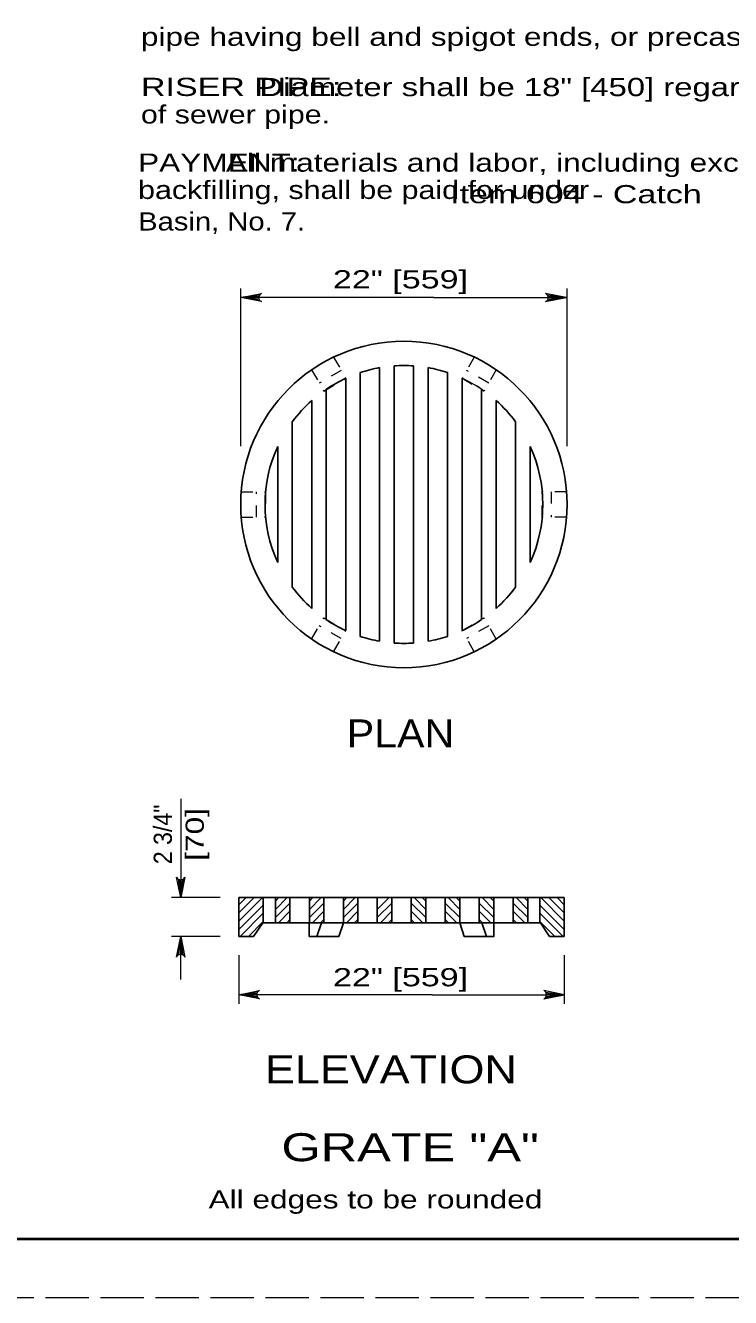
# Model space of a CAD drawing. Extents: x 1302.9 to 1336.9, y 688.5 to 710.5.
# Drawn here: x 1324.42 to 1330.47, y 688.5 to 699.41 of the extents above; entities that cross this region are included whole.
import ezdxf
from ezdxf.enums import TextEntityAlignment as Align

# ---------------------------------------------------------------- set-up
doc = ezdxf.new("R2010")
doc.units = 0
doc.header["$LTSCALE"] = 0.062
doc.linetypes.add('LONG_DASHED', pattern=[7.5, 6, -1.5])
doc.linetypes.add('SHORT_DASHED', pattern=[2.7, 1.5, -1.2])
doc.layers.add('1', color=7, linetype='Continuous', lineweight=13)

msp = doc.modelspace()

# ---------------------------------------------------------------- linework, layer by layer
at = {"layer": '1'}
for p, q in [((1326.26492, 695.80467), (1326.26492, 697.15808)), ((1326.42517, 697.10233), (1326.26492, 697.07992)), ((1326.41975, 697.09125), (1326.26492, 697.07992)), ((1328.89708, 697.10233), (1329.05733, 697.07992)), ((1328.9025, 697.09125), (1329.05733, 697.07992)), ((1329.06583, 695.80467), (1329.06583, 697.15808)), ((1327.922, 697.07992), (1326.26492, 697.07992)), ((1326.41808, 697.07992), (1326.26492, 697.07992)), ((1326.42092, 697.0655), (1326.26492, 697.07992)), ((1326.42708, 697.05517), (1326.26492, 697.07992)), ((1327.922, 697.07992), (1329.05733, 697.07992)), ((1328.89517, 697.05517), (1329.05733, 697.07992)), ((1328.90133, 697.0655), (1329.05733, 697.07992)), ((1328.90417, 697.07992), (1329.05733, 697.07992)), ((1325.74942, 692.78075), (1325.74942, 691.93217)), ((1325.727, 692.09242), (1325.74942, 691.93217)), ((1325.73808, 692.087), (1325.74942, 691.93217)), ((1325.77417, 692.09425), (1325.74942, 691.93217)), ((1325.76383, 692.08817), (1325.74942, 691.93217)), ((1325.74942, 692.08533), (1325.74942, 691.93217)), ((1326.08775, 691.93217), (1325.67125, 691.93217)), ((1326.24917, 691.87108), (1326.31025, 691.93217)), ((1326.24917, 691.8005), (1326.38083, 691.93217)), ((1326.24917, 691.72967), (1326.45167, 691.93217)), ((1326.24917, 691.65908), (1326.45833, 691.86817)), ((1326.5625, 691.90175), (1326.59292, 691.93217)), ((1326.5625, 691.83108), (1326.66358, 691.93217)), ((1326.5625, 691.7605), (1326.68742, 691.88542)), ((1326.85408, 691.90175), (1326.88442, 691.93217)), ((1326.85408, 691.83108), (1326.95508, 691.93217)), ((1326.85408, 691.7605), (1326.979, 691.88542)), ((1327.14558, 691.90175), (1327.176, 691.93217)), ((1327.14558, 691.83108), (1327.24658, 691.93217)), ((1327.14558, 691.7605), (1327.2705, 691.88542)), ((1327.43708, 691.83108), (1327.53817, 691.93217)), ((1327.43708, 691.7605), (1327.56208, 691.88542)), ((1327.85358, 691.7605), (1327.72867, 691.88542)), ((1327.85358, 691.83108), (1327.7525, 691.93217)), ((1327.85358, 691.90175), (1327.82317, 691.93217)), ((1328.14508, 691.7605), (1328.02017, 691.88542)), ((1328.14508, 691.83108), (1328.04408, 691.93217)), ((1328.14508, 691.90175), (1328.11467, 691.93217)), ((1328.43667, 691.7605), (1328.31167, 691.88542)), ((1328.43667, 691.83108), (1328.33558, 691.93217)), ((1328.43667, 691.90175), (1328.40625, 691.93217)), ((1328.72817, 691.7605), (1328.60325, 691.88542)), ((1328.72817, 691.83108), (1328.62717, 691.93217)), ((1328.72817, 691.90175), (1328.69775, 691.93217)), ((1329.0415, 691.65908), (1328.83233, 691.86817)), ((1329.0415, 691.72967), (1328.839, 691.93217)), ((1329.0415, 691.8005), (1328.90983, 691.93217)), ((1329.0415, 691.87108), (1328.9805, 691.93217)), ((1326.25975, 691.599), (1326.45833, 691.79758)), ((1326.58842, 691.71575), (1326.68742, 691.81483)), ((1326.65908, 691.71575), (1326.68742, 691.74417)), ((1326.87992, 691.71575), (1326.979, 691.81483)), ((1326.95058, 691.71575), (1326.979, 691.74417)), ((1327.1715, 691.71575), (1327.2705, 691.81483)), ((1327.24208, 691.71575), (1327.2705, 691.74417)), ((1327.463, 691.71575), (1327.56208, 691.81483)), ((1327.53367, 691.71575), (1327.56208, 691.74417)), ((1327.82767, 691.71575), (1327.72867, 691.81483)), ((1327.757, 691.71575), (1327.72867, 691.74417)), ((1328.11917, 691.71575), (1328.02017, 691.81483)), ((1328.04858, 691.71575), (1328.02017, 691.74417)), ((1328.41075, 691.71575), (1328.31167, 691.81483)), ((1328.34008, 691.71575), (1328.31167, 691.74417)), ((1328.70225, 691.71575), (1328.60325, 691.81483)), ((1328.63158, 691.71575), (1328.60325, 691.74417)), ((1329.03092, 691.599), (1328.83233, 691.79758)), ((1326.3305, 691.599), (1326.45833, 691.72675)), ((1328.96017, 691.599), (1328.83233, 691.72675)), ((1326.08775, 691.599), (1325.67125, 691.599)), ((1325.72458, 691.43692), (1325.74942, 691.599)), ((1325.735, 691.443), (1325.74942, 691.599)), ((1325.74942, 691.479), (1325.74942, 691.599)), ((1325.74942, 691.23042), (1325.74942, 691.599)), ((1325.74942, 691.44583), (1325.74942, 691.599)), ((1325.76075, 691.44417), (1325.74942, 691.599)), ((1325.77183, 691.43875), (1325.74942, 691.599)), ((1326.24917, 691.43758), (1326.24917, 691.02117)), ((1329.0415, 691.43758), (1329.0415, 691.02117)), ((1326.40942, 691.12175), (1326.24917, 691.09933)), ((1326.404, 691.11058), (1326.24917, 691.09933)), ((1327.90625, 691.09933), (1326.24917, 691.09933)), ((1326.40233, 691.09933), (1326.24917, 691.09933)), ((1326.40517, 691.08492), (1326.24917, 691.09933)), ((1326.41133, 691.0745), (1326.24917, 691.09933)), ((1327.90625, 691.09933), (1329.0415, 691.09933)), ((1328.87942, 691.0745), (1329.0415, 691.09933)), ((1328.88125, 691.12175), (1329.0415, 691.09933)), ((1328.8855, 691.08492), (1329.0415, 691.09933)), ((1328.88667, 691.11058), (1329.0415, 691.09933)), ((1328.88833, 691.09933), (1329.0415, 691.09933))]:
    msp.add_line(p, q, dxfattribs=at)
at = {"layer": '1', "linetype": 'SHORT_DASHED'}
for p, q in [((1327.062, 696.56858), (1327.1665, 696.38742)), ((1328.26858, 696.56858), (1328.16408, 696.38742)), ((1326.8725, 696.45917), (1326.97708, 696.27808)), ((1327.12758, 696.45508), (1326.93808, 696.34567)), ((1328.3925, 696.34567), (1328.203, 696.45508)), ((1328.45808, 696.45917), (1328.3535, 696.27808)), ((1326.97708, 696.27808), (1327.1665, 696.38742)), ((1326.26917, 695.41433), (1326.47833, 695.41433)), ((1326.40033, 695.19558), (1326.40033, 695.41433)), ((1326.47833, 695.41433), (1326.47833, 695.19558)), ((1328.85225, 695.19558), (1328.85225, 695.41433)), ((1329.06142, 695.41433), (1328.85225, 695.41433)), ((1328.93025, 695.41433), (1328.93025, 695.19558)), ((1326.26917, 695.19558), (1326.47833, 695.19558)), ((1329.06142, 695.19558), (1328.85225, 695.19558)), ((1326.8725, 694.15067), (1326.97708, 694.33183)), ((1327.12758, 694.15483), (1326.93808, 694.26425)), ((1326.97708, 694.33183), (1327.1665, 694.2225)), ((1328.16408, 694.2225), (1328.3535, 694.33183)), ((1328.3925, 694.26425), (1328.203, 694.15483)), ((1328.45808, 694.15067), (1328.3535, 694.33183)), ((1327.062, 694.04133), (1327.1665, 694.2225)), ((1328.26858, 694.04133), (1328.16408, 694.2225))]:
    msp.add_line(p, q, dxfattribs=at)
at = {"layer": '1', "lineweight": 25}
for p, q in [((1327.2905, 696.43633), (1327.2905, 694.17358)), ((1327.45708, 696.47842), (1327.45708, 694.1315)), ((1327.582, 696.49383), (1327.582, 694.11608)), ((1327.74858, 696.49383), (1327.74858, 694.11608)), ((1327.8735, 696.47842), (1327.8735, 694.1315)), ((1328.04008, 696.43633), (1328.04008, 694.17358)), ((1327.1655, 696.38692), (1327.1655, 694.223)), ((1328.16508, 696.38692), (1328.16508, 694.223)), ((1326.99892, 696.29317), (1326.99892, 694.31675)), ((1328.33167, 696.29317), (1328.33167, 694.31675)), ((1326.874, 696.19625), (1326.874, 694.41367)), ((1328.45658, 696.19625), (1328.45658, 694.41367)), ((1326.70742, 696.01425), (1326.70742, 694.59567)), ((1328.62317, 696.01425), (1328.62317, 694.59567)), ((1326.5825, 695.80308), (1326.5825, 694.80683)), ((1328.74808, 695.80308), (1328.74808, 694.80683)), ((1326.24917, 691.599), (1326.24917, 691.93217)), ((1326.24917, 691.93217), (1329.0415, 691.93217)), ((1326.45833, 691.93217), (1326.45833, 691.71575)), ((1326.5625, 691.93217), (1326.5625, 691.71575)), ((1326.68742, 691.93217), (1326.68742, 691.71575)), ((1326.85408, 691.93217), (1326.85408, 691.71575)), ((1326.979, 691.93217), (1326.979, 691.71575)), ((1327.14558, 691.93217), (1327.14558, 691.71575)), ((1327.2705, 691.93217), (1327.2705, 691.71575)), ((1327.43708, 691.93217), (1327.43708, 691.71575)), ((1327.56208, 691.93217), (1327.56208, 691.71575)), ((1327.72867, 691.93217), (1327.72867, 691.71575)), ((1327.85358, 691.93217), (1327.85358, 691.71575)), ((1328.02017, 691.93217), (1328.02017, 691.71575)), ((1328.14508, 691.93217), (1328.14508, 691.71575)), ((1328.31167, 691.93217), (1328.31167, 691.71575)), ((1328.43667, 691.93217), (1328.43667, 691.71575)), ((1328.60325, 691.93217), (1328.60325, 691.71575)), ((1328.72817, 691.93217), (1328.72817, 691.71575)), ((1328.83233, 691.93217), (1328.83233, 691.71575)), ((1329.0415, 691.599), (1329.0415, 691.93217)), ((1326.45342, 691.71575), (1326.37567, 691.599)), ((1326.45342, 691.71575), (1328.83725, 691.71575)), ((1326.91808, 691.599), (1326.95717, 691.71575)), ((1327.10758, 691.599), (1327.14658, 691.71575)), ((1328.18308, 691.599), (1328.14408, 691.71575)), ((1328.37258, 691.599), (1328.3335, 691.71575)), ((1328.83725, 691.71575), (1328.915, 691.599)), ((1326.24917, 691.599), (1326.37567, 691.599)), ((1329.0415, 691.599), (1328.915, 691.599))]:
    msp.add_line(p, q, dxfattribs=at)
at = {"layer": '1', "linetype": 'SHORT_DASHED', "lineweight": 25}
msp.add_line((1328.16408, 696.38742), (1328.3535, 696.27808), dxfattribs=at)
at = {"layer": '1', "linetype": 'LONG_DASHED'}
msp.add_lwpolyline([(1302.8765, 688.50158), (1336.8765, 688.50158), (1336.8765, 710.50158), (1302.8765, 710.50158)], close=True, dxfattribs=at)
at = {"layer": '1', "lineweight": 25}
for points in [[(1336.3765, 689.00158), (1304.8765, 689.00158), (1304.8765, 710.00158)], [(1326.85258, 691.71575), (1326.85258, 691.599), (1327.10758, 691.599)], [(1328.43817, 691.71575), (1328.43817, 691.599), (1328.18308, 691.599)]]:
    msp.add_lwpolyline(points, dxfattribs=at)
at = {"layer": '1', "lineweight": 40}
msp.add_lwpolyline([(1304.8765, 710.00158), (1336.3765, 710.00158), (1336.3765, 689.00158), (1304.8765, 689.00158)], close=True, dxfattribs=at)
msp.add_lwpolyline([(1304.8765, 710.00158), (1336.3765, 710.00158), (1336.3765, 689.00158), (1304.8765, 689.00158)], close=True, dxfattribs=at)
at = {"layer": '1'}
for points in [[(1326.44192, 697.0445), (1326.26492, 697.07992), (1326.44192, 697.11533)], [(1328.88033, 697.0445), (1329.05733, 697.07992), (1328.88033, 697.11533)], [(1325.78483, 692.10917), (1325.74942, 691.93217), (1325.714, 692.10917)], [(1325.714, 691.422), (1325.74942, 691.599), (1325.78483, 691.422)], [(1326.42617, 691.06392), (1326.24917, 691.09933), (1326.42617, 691.13467)], [(1328.8645, 691.06392), (1329.0415, 691.09933), (1328.8645, 691.13467)]]:
    msp.add_lwpolyline(points, dxfattribs=at)
for centre, start, end in [((1326.45625, 697.08001), 112.08782, 247.91395), ((1328.86601, 697.08001), 292.08605, 67.91218), ((1325.74936, 692.12348), 202.08782, 337.91395), ((1325.74944, 691.40775), 22.08782, 157.91395), ((1326.44046, 691.09937), 112.08782, 247.91395), ((1328.85022, 691.09937), 292.08605, 67.91218)]:
    msp.add_arc(centre, 0.0382, start, end, dxfattribs=at)
at = {"layer": '1', "lineweight": 25}
msp.add_ellipse((1327.66533, 695.30499), major_axis=(1.40038, 0), ratio=0.999895, dxfattribs=at)
for major_axis, start_param, end_param in [((1.19194, 0), 1.74640045, 1.89068977), ((1.19194, 0), 1.50085812, 1.64073453), ((1.19194, 0), 1.25090288, 1.39519221), ((1.19194, 0), 2.00346767, 2.16403195), ((1.19194, 0), 2.2967655, 2.50418527), ((1.19194, 0), 0.63742003, 0.84481261), ((1.19194, 0), 2.71037057, 3.57281474), ((-1.19194, 0), 2.71037057, 3.57281474), ((1.19194, 0), 3.77901269, 3.98640527), ((1.19194, 0), 5.43837269, 5.64576527), ((1.19194, 0), 4.11914987, 4.27972894), ((1.19194, 0), 5.14504902, 5.30562809), ((1.19194, 0), 4.39249553, 4.53678486), ((1.19194, 0), 4.8879931, 5.03228243), ((1.19194, 0), 4.64245078, 4.78232718)]:
    msp.add_ellipse((1327.66529, 695.30499), major_axis=major_axis, ratio=0.999895, start_param=start_param, end_param=end_param, dxfattribs=at)
at = {"layer": '1'}
for centre, major_axis, start_param, end_param in [((1327.66529, 695.30499), (-1.19194, 0), 5.14504902, 5.30562809), ((1327.66529, 695.30499), (1.19194, 0), 0.97755722, 1.13813628), ((1327.66529, 695.30499), (1.19194, 0), 0.97755722, 1.13813628), ((1327.66529, 695.30499), (-1.19194, 0), 4.11915336, 4.27971764), ((1327.66529, 695.30499), (-1.19194, 0), 4.09785147, 4.25843054), ((1327.66529, 695.30499), (-1.19194, 0), 4.09785147, 4.25843054), ((1327.66529, 695.30499), (-1.19194, 0), 0.97755722, 1.13813628), ((1327.64538, 691.824), (1.40038, 0), 3.21873475, 3.21893362), ((1327.6453, 691.824), (-1.40038, 0), 3.06425168, 3.06445056)]:
    msp.add_ellipse(centre, major_axis=major_axis, ratio=0.999895, start_param=start_param, end_param=end_param, dxfattribs=at)

# ---------------------------------------------------------------- texts
for s, height, width, p in [('pipe having bell and spigot ends, or precast as noted above.', 0.156, 1.3, (1325.40817, 699.239)), ('RISER PIPE:', 0.156, 1.4, (1325.40817, 698.80883)), ('             Diameter shall be 18" [450] regardless of size ', 0.156, 1.35, (1325.40817, 698.8075)), ('of sewer pipe.', 0.156, 1.25, (1325.40817, 698.57283)), ('PAYMENT: ', 0.156, 1.3, (1325.38417, 698.15942)), ('          All materials and labor, including excavation and', 0.156, 1.3, (1325.38417, 698.15942)), ('backfilling, shall be paid for under ', 0.156, 1.25, (1325.38417, 697.92542)), ('                                 Item 604 - Catch ', 0.156, 1.4, (1325.38425, 697.88875)), ('Basin, No. 7.', 0.156, 1.2, (1325.38425, 697.65475)), ('PLAN', 0.24, 1.1, (1327.17458, 693.22058)), ('ELEVATION', 0.24, 1.2, (1326.47267, 690.33883)), ('GRATE "A"', 0.24, 1.35, (1326.61392, 689.67133)), ('All edges to be rounded', 0.156, 1.3, (1325.98858, 689.26583))]:
    msp.add_text(s, height=height, dxfattribs=dict(at, width=width)).set_placement(p)
at = {"layer": '1', "width": 1.4}
for p in [(1327.63546, 697.15842), (1327.63629, 691.1715)]:
    msp.add_text('22" [559]', height=0.156, dxfattribs=at).set_placement(p, align=Align.CENTER)
at = {"layer": '1'}
for s, width, p in [('2 3/4"', 0.95, (1325.67408, 692.47471)), ('[70]', 1.3, (1325.94808, 692.47467))]:
    msp.add_text(s, height=0.156, rotation=90, dxfattribs=dict(at, width=width)).set_placement(p, align=Align.CENTER)

doc.saveas('drawing.dxf')
